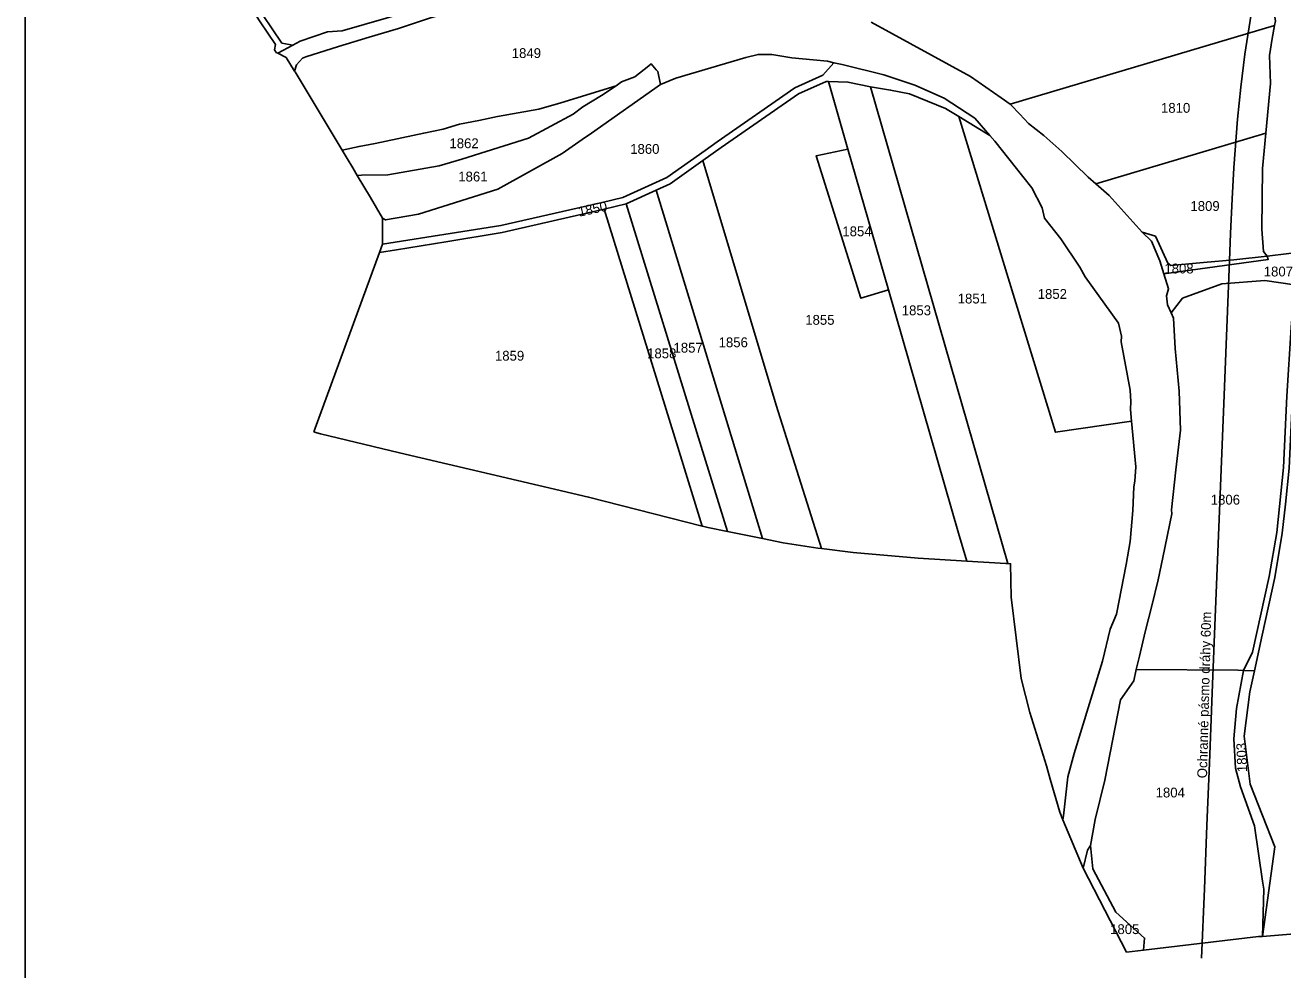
# Model space of a CAD drawing. Extents: x -584305 to -582773, y -1166873 to -1164718.
# Drawn here: x -584305 to -583410, y -1166148 to -1165476 of the extents above; entities that cross this region are included whole.
import ezdxf

# ---------------------------------------------------------------- set-up
doc = ezdxf.new("R2010")
doc.units = 0
for name, color, linetype in [('37', 7, 'Continuous'), ('_Rám HC11-R', 7, 'Continuous'), ('Hranice parcel', 7, 'Continuous'), ('Parcelní čísla', 7, 'Continuous')]:
    doc.layers.add(name, color=color, linetype=linetype)

msp = doc.modelspace()

# ---------------------------------------------------------------- linework, layer by layer
at = {"layer": '37'}
msp.add_lwpolyline([(-583467.5, -1166140.03), (-583465.54, -1166090.53), (-583463.73, -1166045.43), (-583461.96, -1166001.15), (-583459.73, -1165944.95), (-583457.83, -1165897.51), (-583455.75, -1165845), (-583453.88, -1165797.97), (-583451.76, -1165745.07), (-583447.63, -1165643.26), (-583446.86, -1165623.99), (-583445.81, -1165599.54), (-583444.66, -1165577.37), (-583442.03, -1165542.78), (-583439.67, -1165520.04), (-583436.68, -1165496.55), (-583431.49, -1165463.54), (-583426.63, -1165437.64), (-583422.05, -1165416.22), (-583417.44, -1165396.54), (-583410.09, -1165367.4), (-583389.99, -1165290.81)], dxfattribs=at)
at = {"layer": '_Rám HC11-R'}
msp.add_lwpolyline([(-582820.03, -1166873.12), (-582820.03, -1164773.12), (-584305.03, -1164773.12), (-584305.03, -1166873.12), (-582820.03, -1166873.12)], dxfattribs=at)
at = {"layer": 'Hranice parcel'}
for p, q in [((-583415.62, -1165476.12), (-583603.8, -1165532.05)), ((-584114.38, -1165490.11), (-584125.04, -1165495.82)), ((-584126.27, -1165495.2), (-584127.54, -1165493.29)), ((-584125.04, -1165495.82), (-584126.27, -1165495.2)), ((-584119.16, -1165498.78), (-584125.04, -1165495.82)), ((-584113.23, -1165508.57), (-584119.16, -1165498.78)), ((-583733.21, -1165515.97), (-583719.48, -1165564.15)), ((-583640.44, -1165540.93), (-583618.26, -1165554.37)), ((-583421.75, -1165552.72), (-583542.88, -1165588.73)), ((-584075.72, -1165570.64), (-584079.31, -1165564.7)), ((-584071.78, -1165577.35), (-584075.72, -1165570.64)), ((-583719.48, -1165564.15), (-583690.45, -1165664.16)), ((-584068.64, -1165582.84), (-584071.78, -1165577.35)), ((-583877.08, -1165602.99), (-583855.8, -1165593.22)), ((-583892.86, -1165606.78), (-583877.08, -1165602.99)), ((-584050.73, -1165617.34), (-584050.73, -1165613.13)), ((-584050.73, -1165620.55), (-584050.73, -1165617.34)), ((-584050.72, -1165631.79), (-584050.73, -1165620.55)), ((-584052.87, -1165637.59), (-584050.72, -1165631.79)), ((-584099.56, -1165765.35), (-584052.87, -1165637.59)), ((-583405.42, -1165638.41), (-583420.83, -1165640.2)), ((-584097.49, -1165765.92), (-584099.56, -1165765.35)), ((-583821.92, -1165832.64), (-583823.09, -1165832.34)), ((-583780.01, -1165841.28), (-583804.95, -1165836.2)), ((-583429.98, -1165935.47), (-583437.63, -1165935.06)), ((-583568.45, -1166036.07), (-583575.22, -1166012.56)), ((-583566.24, -1166041.4), (-583568.45, -1166036.07)), ((-583551.93, -1166075.89), (-583566.24, -1166041.4)), ((-583521.06, -1166135.71), (-583551.93, -1166075.89)), ((-583426.97, -1166124.55), (-583508.93, -1166134.27)), ((-583424.26, -1166124.52), (-583426.97, -1166124.55)), ((-583395.78, -1166122.08), (-583424.26, -1166124.52)), ((-583508.93, -1166134.27), (-583521.06, -1166135.71))]:
    msp.add_line(p, q, dxfattribs=at)
for points in [[(-583974.84, -1165282.18), (-583954.94, -1165348.93), (-583952.24, -1165368.22), (-583945.43, -1165383.61), (-583944.47, -1165391.31), (-583943.78, -1165404.8), (-583949.92, -1165432.02), (-583955.76, -1165438.7), (-583979.99, -1165450.08), (-583993.12, -1165453.3), (-584003.91, -1165458.08), (-584032.27, -1165466.39), (-584079.46, -1165479.88), (-584089.8, -1165480.66), (-584109.32, -1165487.31), (-584114.38, -1165490.11)], [(-583415.62, -1165476.12), (-583415.02, -1165472.65), (-583420.22, -1165443.6), (-583448.97, -1165365.39), (-583458.92, -1165347.2), (-583477.78, -1165313.78)], [(-584127.54, -1165493.29), (-584126.7, -1165489.49), (-584137.68, -1165473.5), (-584145.63, -1165461.29), (-584156.82, -1165446.27), (-584169.56, -1165428.1), (-584181.07, -1165412.34), (-584191.49, -1165397.12), (-584200.37, -1165384.95), (-584203.2, -1165381.2)], [(-584199.68, -1165378.89), (-584142.41, -1165458.77), (-584122.2, -1165488.62), (-584114.38, -1165490.11)], [(-583953.93, -1165452.64), (-583988.32, -1165462.57), (-584017.19, -1165470.76), (-584039.23, -1165478.13), (-584060.02, -1165484.43), (-584082.01, -1165490.99), (-584105.29, -1165498.3), (-584107.56, -1165499.38), (-584111.74, -1165503.97), (-584113.23, -1165508.57)], [(-583702.75, -1165473.63), (-583631.95, -1165512.27), (-583610.25, -1165527.42), (-583603.8, -1165532.05)], [(-583421.75, -1165552.72), (-583418.41, -1165517.42), (-583419.25, -1165497.44), (-583417.19, -1165485.32), (-583415.62, -1165476.12)], [(-583852.84, -1165517.96), (-583841.81, -1165513.57), (-583792.02, -1165498.71), (-583783.27, -1165496.64), (-583773.53, -1165496.7), (-583759.18, -1165499.18), (-583743.94, -1165500.5), (-583733.96, -1165501.55), (-583729.44, -1165502.52)], [(-583729.44, -1165502.52), (-583737.13, -1165511.45), (-583757.05, -1165520.41), (-583812.42, -1165558.83), (-583821.05, -1165564.92), (-583848.32, -1165584.28), (-583879.47, -1165598.58), (-583894.37, -1165601.99), (-583966.35, -1165618.48), (-584050.72, -1165631.79)], [(-583884.38, -1165518.88), (-583880.45, -1165516.15), (-583871.04, -1165512.47), (-583861.15, -1165504.68), (-583859.41, -1165503.31), (-583855.73, -1165507.58), (-583854.66, -1165508.82), (-583852.84, -1165517.96)], [(-583729.44, -1165502.52), (-583723.45, -1165503.81), (-583693.75, -1165511.27), (-583671.65, -1165518.59), (-583650.76, -1165527.82), (-583628.98, -1165542.04), (-583618.26, -1165554.37)], [(-584079.31, -1165564.7), (-584112.91, -1165509.1), (-584113.23, -1165508.57)], [(-583822.49, -1165572.22), (-583809.53, -1165562.91), (-583754.58, -1165524.78), (-583734.84, -1165516.01), (-583733.21, -1165515.97)], [(-583733.21, -1165515.97), (-583719.34, -1165516.31), (-583703.35, -1165519.71)], [(-584079.31, -1165564.7), (-584067.26, -1165562.13), (-584055.78, -1165559.93), (-584021.24, -1165552.6), (-584007.47, -1165549.85), (-583995.87, -1165546.23), (-583982.05, -1165543.63), (-583968.75, -1165540.77), (-583939.42, -1165535.53), (-583923.65, -1165531.17), (-583884.38, -1165518.88)], [(-583884.38, -1165518.88), (-583894.71, -1165525.8), (-583907.92, -1165533.9), (-583914.98, -1165539.25), (-583946.77, -1165556.33), (-583994.11, -1165571.24), (-584010.35, -1165575.94), (-584046.73, -1165582.3), (-584065.53, -1165582.57), (-584068.64, -1165582.84)], [(-583852.84, -1165517.96), (-583901.89, -1165552.75), (-583908.41, -1165557.28), (-583922.62, -1165567.15), (-583968.55, -1165592.5), (-584025.08, -1165610.45), (-584048.48, -1165614.4), (-584050.73, -1165613.13)], [(-583703.35, -1165519.71), (-583654.39, -1165689.39), (-583605.43, -1165859.07)], [(-583703.35, -1165519.71), (-583688.99, -1165522), (-583675.49, -1165524.68), (-583649.9, -1165535.2), (-583640.44, -1165540.93)], [(-583603.8, -1165532.05), (-583603.27, -1165532.43), (-583597.03, -1165539.1), (-583590.78, -1165545.76), (-583579.84, -1165554.27), (-583567.14, -1165565.76), (-583548.31, -1165584.01), (-583542.88, -1165588.73)], [(-583517.36, -1165757.73), (-583571.63, -1165765.62), (-583605.33, -1165655.58), (-583640.44, -1165540.93)], [(-583420.83, -1165640.2), (-583423.48, -1165636.82), (-583424.67, -1165621.14), (-583424.4, -1165599.47), (-583424.12, -1165577.81), (-583421.75, -1165552.72)], [(-583618.26, -1165554.37), (-583614.81, -1165558.32), (-583594.71, -1165583.65), (-583588.42, -1165591.55), (-583580.97, -1165605.8), (-583579.42, -1165613.24), (-583567.62, -1165627.95), (-583554.32, -1165648.02), (-583550.34, -1165655.03), (-583526.72, -1165688.02), (-583524.66, -1165697.3), (-583524.81, -1165701.28), (-583518.36, -1165735.56), (-583517.9, -1165743.74), (-583518.13, -1165749.48), (-583517.36, -1165757.73)], [(-583719.48, -1165564.15), (-583741.94, -1165568.88), (-583710.14, -1165670.14), (-583690.45, -1165664.16)], [(-583855.8, -1165593.22), (-583845.83, -1165588.64), (-583822.49, -1165572.22)], [(-583822.49, -1165572.22), (-583770.36, -1165746.36), (-583738.18, -1165848.42)], [(-584050.73, -1165613.13), (-584059.21, -1165598.49), (-584068.64, -1165582.84)], [(-583542.88, -1165588.73), (-583533.31, -1165597.07), (-583509.78, -1165623.06)], [(-583855.8, -1165593.22), (-583804.04, -1165762.63), (-583780.01, -1165841.28)], [(-584052.87, -1165637.59), (-584040.7, -1165635.63), (-584005.49, -1165629.97), (-583965.39, -1165623.39), (-583892.86, -1165606.78)], [(-583892.86, -1165606.78), (-583839.48, -1165779.37), (-583823.09, -1165832.34)], [(-583877.08, -1165602.99), (-583823.69, -1165775.61), (-583804.95, -1165836.2)], [(-583420.83, -1165640.2), (-583444.47, -1165642.96), (-583466.11, -1165644.8), (-583489.37, -1165646.78), (-583491.58, -1165645.28), (-583500.37, -1165626.09), (-583509.78, -1165623.06)], [(-583509.78, -1165623.06), (-583503.29, -1165629.64), (-583497.15, -1165643.66), (-583494.35, -1165652.77)], [(-583420.83, -1165640.2), (-583420.13, -1165642.5), (-583494.35, -1165652.77)], [(-583405.42, -1165638.41), (-583394.48, -1165637.13), (-583393.83, -1165639.42), (-583399.74, -1165691.26), (-583402.75, -1165740.2), (-583405.14, -1165791.1), (-583407.9, -1165816.75), (-583410.07, -1165837.49), (-583415.38, -1165868.98), (-583424.37, -1165909.91), (-583429.98, -1165935.47)], [(-583494.35, -1165652.77), (-583491.08, -1165663.43), (-583492.56, -1165668.46), (-583491.84, -1165674.97), (-583489.23, -1165680.56)], [(-583437.63, -1165935.06), (-583431.38, -1165922.1), (-583419.31, -1165868.22), (-583414.03, -1165836.86), (-583409.13, -1165790.79), (-583406.74, -1165739.98), (-583403.73, -1165691.01), (-583401.29, -1165660.74), (-583422.41, -1165657.63), (-583453.17, -1165659.96), (-583481.05, -1165670.05), (-583489.23, -1165680.56)], [(-583690.45, -1165664.16), (-583640.48, -1165837.32), (-583634.72, -1165857.29)], [(-583489.23, -1165680.56), (-583487.51, -1165684.26), (-583486.43, -1165705.91), (-583483.46, -1165736.23), (-583482.45, -1165764.15), (-583485.79, -1165792.34), (-583489.01, -1165820.82), (-583488.83, -1165823.76), (-583495.04, -1165854.79), (-583498.41, -1165870.54), (-583503.02, -1165889.04), (-583507.62, -1165907.55), (-583511.73, -1165925.04), (-583514, -1165934.51)], [(-583517.36, -1165757.73), (-583514.32, -1165790.16), (-583515.07, -1165800.5), (-583515.83, -1165804.41), (-583516.39, -1165821.2), (-583518.41, -1165843.31), (-583521.2, -1165859.69), (-583528.03, -1165895.13), (-583532.66, -1165905.77), (-583538.01, -1165928.56), (-583547.33, -1165958.68), (-583558.27, -1165994.28), (-583562.85, -1166010.78), (-583565.88, -1166038.71), (-583566.24, -1166041.4)], [(-583823.09, -1165832.34), (-583903.94, -1165811.75), (-583939.33, -1165803.5), (-584038.42, -1165780.34), (-584094.82, -1165766.65), (-584097.49, -1165765.92)], [(-583804.95, -1165836.2), (-583819, -1165833.34), (-583821.92, -1165832.64)], [(-583738.18, -1165848.42), (-583740.78, -1165848.11), (-583765.43, -1165844.25), (-583780.01, -1165841.28)], [(-583634.72, -1165857.29), (-583669.38, -1165855.17), (-583715.58, -1165851.13), (-583738.18, -1165848.42)], [(-583605.43, -1165859.07), (-583606.97, -1165858.98), (-583634.72, -1165857.29)], [(-583575.22, -1166012.56), (-583577.98, -1166002.97), (-583589.73, -1165965.16), (-583595.87, -1165940.9), (-583603.04, -1165883.03), (-583603.5, -1165859.19), (-583605.43, -1165859.07)], [(-583514, -1165934.51), (-583515.84, -1165942.53), (-583525.33, -1165956.01), (-583536.41, -1166013.21), (-583543.31, -1166041.15), (-583546.64, -1166059.79)], [(-583437.63, -1165935.06), (-583441.82, -1165934.91), (-583514, -1165934.51)], [(-583437.63, -1165935.06), (-583442.76, -1165962.33), (-583444.67, -1165983.77), (-583443.42, -1166004.77), (-583439.8, -1166018.02), (-583429.88, -1166045.64), (-583424.27, -1166085.25), (-583423.21, -1166090.9), (-583424.26, -1166124.52)], [(-583429.98, -1165935.47), (-583433.28, -1165950.47), (-583437.28, -1165981.91), (-583433.06, -1166016.1), (-583415.29, -1166060.7), (-583424.26, -1166124.52)], [(-583546.64, -1166059.79), (-583548.75, -1166063.07), (-583551.93, -1166075.89)], [(-583546.64, -1166059.79), (-583545.02, -1166076.29), (-583528.47, -1166107.31), (-583508.13, -1166125.63), (-583508.93, -1166134.27)]]:
    msp.add_lwpolyline(points, dxfattribs=at)

# ---------------------------------------------------------------- texts
msp.add_text('Ochranné pásmo dráhy 60m', height=7, rotation=88.52387).set_placement((-583463.68, -1166011.94))
at = {"layer": 'Parcelní čísla'}
for s, p in [('1849', (-583958.61, -1165499.2)), ('1810', (-583496.42, -1165538.17)), ('1862', (-584002.98, -1165563.38)), ('1860', (-583874.3, -1165567.42)), ('1861', (-583996.7, -1165587.07)), ('1809', (-583475.47, -1165608.04)), ('1854', (-583723.27, -1165626.07)), ('1808', (-583494.02, -1165652.54)), ('1807', (-583423.28, -1165654.68)), ('1851', (-583641.14, -1165673.92)), ('1852', (-583584.19, -1165670.65)), ('1853', (-583680.97, -1165682.29)), ('1855', (-583749.68, -1165689.08)), ('1857', (-583843.46, -1165708.89)), ('1856', (-583811.35, -1165705.08)), ('1859', (-583970.57, -1165714.62)), ('1858', (-583862.27, -1165712.95)), ('1806', (-583461, -1165817.08)), ('1804', (-583500.24, -1166025.53)), ('1805', (-583532.63, -1166122.8))]:
    msp.add_text(s, height=7, dxfattribs=at).set_placement(p)
for s, rotation, p in [('1850', 12, (-583910.53, -1165612.17)), ('1803', 92, (-583435.12, -1166007.41))]:
    msp.add_text(s, height=7, rotation=rotation, dxfattribs=at).set_placement(p)

doc.saveas('drawing.dxf')
